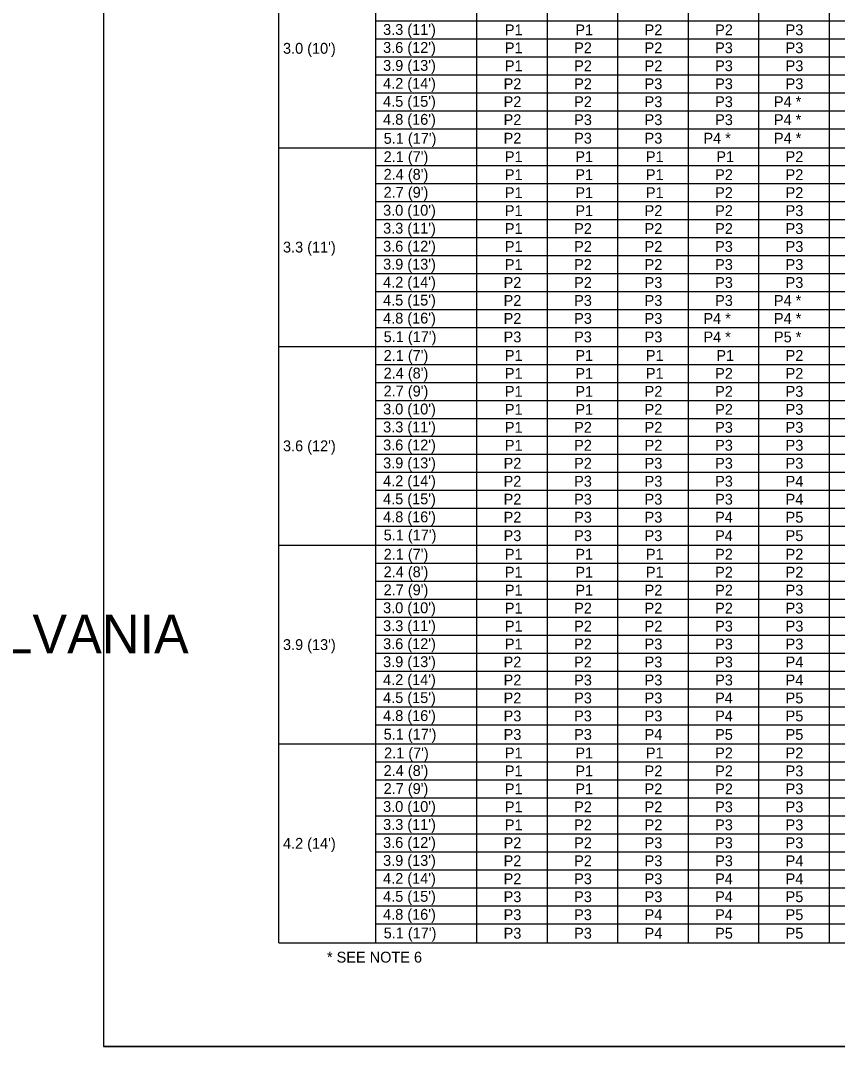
# Model space of a CAD drawing. Extents: x 637580 to 641008, y 294594 to 295782.
# Drawn here: x 638438.3 to 638664.4, y 295202.6 to 295486.5 of the extents above; entities that cross this region are included whole.
import ezdxf

# ---------------------------------------------------------------- set-up
doc = ezdxf.new("R2010")
doc.units = 0
doc.layers.add('1', color=7, linetype='Continuous')
doc.layers.add('2', color=7, linetype='Continuous')

msp = doc.modelspace()

# ---------------------------------------------------------------- linework, layer by layer
at = {"layer": '1'}
for p, q in [((638461.31, 295766.63), (638461.31, 295202.63)), ((638509.81, 295231.34), (638509.81, 295750.63)), ((638536.61, 295231.34), (638536.61, 295742.95)), ((638564.61, 295231.34), (638564.61, 295742.95)), ((638584.12, 295231.34), (638584.12, 295735.61)), ((638603.63, 295231.34), (638603.63, 295735.61)), ((638623.14, 295231.34), (638623.14, 295735.61)), ((638642.64, 295231.34), (638642.64, 295735.61)), ((638662.15, 295231.34), (638662.15, 295735.61)), ((638509.81, 295451.3), (638876.73, 295451.3)), ((638509.81, 295396.31), (638876.73, 295396.31)), ((638509.81, 295341.32), (638876.73, 295341.32)), ((638509.81, 295286.33), (638876.73, 295286.33)), ((638509.81, 295231.34), (638876.73, 295231.34)), ((639247.31, 295202.63), (638461.31, 295202.63)), ((638461.31, 295202.63), (639047.31, 295202.63))]:
    msp.add_line(p, q, dxfattribs=at)
at = {"layer": '2'}
for p, q in [((638536.61, 295486.4), (638876.73, 295486.4)), ((638536.61, 295481.43), (638876.73, 295481.43)), ((638536.61, 295476.45), (638876.73, 295476.45)), ((638536.61, 295471.48), (638876.73, 295471.48)), ((638536.61, 295466.51), (638876.73, 295466.51)), ((638536.61, 295461.54), (638876.73, 295461.54)), ((638536.61, 295456.56), (638876.73, 295456.56)), ((638536.61, 295446.33), (638876.73, 295446.33)), ((638536.61, 295441.35), (638876.73, 295441.35)), ((638536.61, 295436.38), (638876.73, 295436.38)), ((638536.61, 295431.41), (638876.73, 295431.41)), ((638536.61, 295426.44), (638876.73, 295426.44)), ((638536.61, 295421.46), (638876.73, 295421.46)), ((638536.61, 295416.49), (638876.73, 295416.49)), ((638536.61, 295411.52), (638876.73, 295411.52)), ((638536.61, 295406.55), (638876.73, 295406.55)), ((638536.61, 295401.57), (638876.73, 295401.57)), ((638536.61, 295391.34), (638876.73, 295391.34)), ((638536.61, 295386.36), (638876.73, 295386.36)), ((638536.61, 295381.39), (638876.73, 295381.39)), ((638536.61, 295376.42), (638876.73, 295376.42)), ((638536.61, 295371.45), (638876.73, 295371.45)), ((638536.61, 295366.47), (638876.73, 295366.47)), ((638536.61, 295361.5), (638876.73, 295361.5)), ((638536.61, 295356.53), (638876.73, 295356.53)), ((638536.61, 295351.56), (638876.73, 295351.56)), ((638536.61, 295346.58), (638876.73, 295346.58)), ((638536.61, 295336.35), (638876.73, 295336.35)), ((638536.61, 295331.37), (638876.73, 295331.37)), ((638536.61, 295326.4), (638876.73, 295326.4)), ((638536.61, 295321.43), (638876.73, 295321.43)), ((638536.61, 295316.46), (638876.73, 295316.46)), ((638536.61, 295311.48), (638876.73, 295311.48)), ((638536.61, 295306.51), (638876.73, 295306.51)), ((638536.61, 295301.54), (638876.73, 295301.54)), ((638536.61, 295296.57), (638876.73, 295296.57)), ((638536.61, 295291.59), (638876.73, 295291.59)), ((638536.61, 295281.36), (638876.73, 295281.36)), ((638536.61, 295276.38), (638876.73, 295276.38)), ((638536.61, 295271.41), (638876.73, 295271.41)), ((638536.61, 295266.44), (638876.73, 295266.44)), ((638536.61, 295261.47), (638876.73, 295261.47)), ((638536.61, 295256.49), (638876.73, 295256.49)), ((638536.61, 295251.52), (638876.73, 295251.52)), ((638536.61, 295246.55), (638876.73, 295246.55)), ((638536.61, 295241.58), (638876.73, 295241.58)), ((638536.61, 295236.6), (638876.73, 295236.6))]:
    msp.add_line(p, q, dxfattribs=at)

# ---------------------------------------------------------------- texts
at = {"layer": '1'}
for s, height, p in [("3.3 (11')", 3, (638538.67, 295482.51)), ('P1', 3, (638572.36, 295482.41)), ('P1', 3, (638591.87, 295482.41)), ('P2', 3, (638611.03, 295482.41)), ('P2', 3, (638630.54, 295482.41)), ('P3', 3, (638650.05, 295482.41)), ("3.0 (10')", 3, (638510.97, 295477.29)), ("3.6 (12')", 3, (638538.67, 295477.53)), ('P1', 3, (638572.36, 295477.44)), ('P2', 3, (638591.53, 295477.44)), ('P2', 3, (638611.03, 295477.44)), ('P3', 3, (638630.54, 295477.44)), ('P3', 3, (638650.05, 295477.44)), ("3.9 (13')", 3, (638538.67, 295472.56)), ('P1', 3, (638572.36, 295472.47)), ('P2', 3, (638591.53, 295472.47)), ('P2', 3, (638611.03, 295472.47)), ('P3', 3, (638630.54, 295472.47)), ('P3', 3, (638650.05, 295472.47)), ("4.2 (14')", 3, (638538.67, 295467.59)), ('P2', 3, (638572.02, 295467.49)), ('P2', 3, (638591.53, 295467.49)), ('P3', 3, (638611.03, 295467.49)), ('P3', 3, (638630.54, 295467.49)), ('P3', 3, (638650.05, 295467.49)), ("4.5 (15')", 3, (638538.67, 295462.62)), ('P2', 3, (638572.02, 295462.52)), ('P2', 3, (638591.53, 295462.52)), ('P3', 3, (638611.03, 295462.52)), ('P3', 3, (638630.54, 295462.52)), ('P4 *', 3, (638646.82, 295462.52)), ("4.8 (16')", 3, (638538.67, 295457.64)), ('P2', 3, (638572.02, 295457.55)), ('P3', 3, (638591.53, 295457.55)), ('P3', 3, (638611.03, 295457.55)), ('P3', 3, (638630.54, 295457.55)), ('P4 *', 3, (638646.82, 295457.55)), ("5.1 (17')", 3, (638538.83, 295452.37)), ('P2', 3, (638572.02, 295452.43)), ('P3', 3, (638591.53, 295452.43)), ('P3', 3, (638611.03, 295452.43)), ('P4 *', 3, (638627.31, 295452.43)), ('P4 *', 3, (638646.82, 295452.43)), ("2.1 (7')", 3, (638538.82, 295447.31)), ('P1', 3, (638572.36, 295447.31)), ('P1', 3, (638591.87, 295447.31)), ('P1', 3, (638611.38, 295447.31)), ('P1', 3, (638630.88, 295447.31)), ('P2', 3, (638650.05, 295447.31)), ("2.4 (8')", 3, (638538.82, 295442.43)), ('P1', 3, (638572.36, 295442.34)), ('P1', 3, (638591.87, 295442.34)), ('P1', 3, (638611.38, 295442.34)), ('P2', 3, (638630.54, 295442.34)), ('P2', 3, (638650.05, 295442.34)), ("2.7 (9')", 3, (638538.82, 295437.46)), ('P1', 3, (638572.36, 295437.37)), ('P1', 3, (638591.87, 295437.37)), ('P1', 3, (638611.38, 295437.37)), ('P2', 3, (638630.54, 295437.37)), ('P2', 3, (638650.05, 295437.37)), ("3.0 (10')", 3, (638538.67, 295432.49)), ('P1', 3, (638572.36, 295432.39)), ('P1', 3, (638591.87, 295432.39)), ('P2', 3, (638611.03, 295432.39)), ('P2', 3, (638630.54, 295432.39)), ('P3', 3, (638650.05, 295432.39)), ("3.3 (11')", 3, (638538.67, 295427.52)), ('P1', 3, (638572.36, 295427.42)), ('P2', 3, (638591.53, 295427.42)), ('P2', 3, (638611.03, 295427.42)), ('P2', 3, (638630.54, 295427.42)), ('P3', 3, (638650.05, 295427.42)), ("3.3 (11')", 3, (638510.97, 295422.3)), ("3.6 (12')", 3, (638538.67, 295422.54)), ('P1', 3, (638572.36, 295422.45)), ('P2', 3, (638591.53, 295422.45)), ('P2', 3, (638611.03, 295422.45)), ('P3', 3, (638630.54, 295422.45)), ('P3', 3, (638650.05, 295422.45)), ("3.9 (13')", 3, (638538.67, 295417.57)), ('P1', 3, (638572.36, 295417.48)), ('P2', 3, (638591.53, 295417.48)), ('P2', 3, (638611.03, 295417.48)), ('P3', 3, (638630.54, 295417.48)), ('P3', 3, (638650.05, 295417.48)), ("4.2 (14')", 3, (638538.67, 295412.6)), ('P2', 3, (638572.02, 295412.5)), ('P2', 3, (638591.53, 295412.5)), ('P3', 3, (638611.03, 295412.5)), ('P3', 3, (638630.54, 295412.5)), ('P3', 3, (638650.05, 295412.5)), ("4.5 (15')", 3, (638538.67, 295407.63)), ('P2', 3, (638572.02, 295407.53)), ('P3', 3, (638591.53, 295407.53)), ('P3', 3, (638611.03, 295407.53)), ('P3', 3, (638630.54, 295407.53)), ('P4 *', 3, (638646.82, 295407.53)), ("4.8 (16')", 3, (638538.67, 295402.65)), ('P2', 3, (638572.02, 295402.56)), ('P3', 3, (638591.53, 295402.56)), ('P3', 3, (638611.03, 295402.56)), ('P4 *', 3, (638627.31, 295402.56)), ('P4 *', 3, (638646.82, 295402.56)), ("5.1 (17')", 3, (638538.83, 295397.5)), ('P3', 3, (638572.02, 295397.44)), ('P3', 3, (638591.53, 295397.44)), ('P3', 3, (638611.03, 295397.44)), ('P4 *', 3, (638627.31, 295397.44)), ('P5 *', 3, (638646.82, 295397.44)), ("2.1 (7')", 3, (638538.82, 295392.32)), ('P1', 3, (638572.36, 295392.32)), ('P1', 3, (638591.87, 295392.32)), ('P1', 3, (638611.38, 295392.32)), ('P1', 3, (638630.88, 295392.32)), ('P2', 3, (638650.05, 295392.32)), ("2.4 (8')", 3, (638538.82, 295387.44)), ('P1', 3, (638572.36, 295387.35)), ('P1', 3, (638591.87, 295387.35)), ('P1', 3, (638611.38, 295387.35)), ('P2', 3, (638630.54, 295387.35)), ('P2', 3, (638650.05, 295387.35)), ("2.7 (9')", 3, (638538.82, 295382.47)), ('P1', 3, (638572.36, 295382.38)), ('P1', 3, (638591.87, 295382.38)), ('P2', 3, (638611.03, 295382.38)), ('P2', 3, (638630.54, 295382.38)), ('P3', 3, (638650.05, 295382.38)), ("3.0 (10')", 3, (638538.67, 295377.5)), ('P1', 3, (638572.36, 295377.4)), ('P1', 3, (638591.87, 295377.4)), ('P2', 3, (638611.03, 295377.4)), ('P2', 3, (638630.54, 295377.4)), ('P3', 3, (638650.05, 295377.4)), ("3.3 (11')", 3, (638538.67, 295372.53)), ('P1', 3, (638572.36, 295372.43)), ('P2', 3, (638591.53, 295372.43)), ('P2', 3, (638611.03, 295372.43)), ('P3', 3, (638630.54, 295372.43)), ('P3', 3, (638650.05, 295372.43)), ("3.6 (12')", 3, (638538.67, 295367.55)), ("3.6 (12')", 3, (638510.97, 295367.31)), ('P1', 3, (638572.36, 295367.46)), ('P2', 3, (638591.53, 295367.46)), ('P2', 3, (638611.03, 295367.46)), ('P3', 3, (638630.54, 295367.46)), ('P3', 3, (638650.05, 295367.46)), ("3.9 (13')", 3, (638538.67, 295362.58)), ('P2', 3, (638572.02, 295362.49)), ('P2', 3, (638591.53, 295362.49)), ('P3', 3, (638611.03, 295362.49)), ('P3', 3, (638630.54, 295362.49)), ('P3', 3, (638650.05, 295362.49)), ("4.2 (14')", 3, (638538.67, 295357.61)), ('P2', 3, (638572.02, 295357.51)), ('P3', 3, (638591.53, 295357.51)), ('P3', 3, (638611.03, 295357.51)), ('P3', 3, (638630.54, 295357.51)), ('P4', 3, (638650.05, 295357.51)), ("4.5 (15')", 3, (638538.67, 295352.64)), ('P2', 3, (638572.02, 295352.54)), ('P3', 3, (638591.53, 295352.54)), ('P3', 3, (638611.03, 295352.54)), ('P3', 3, (638630.54, 295352.54)), ('P4', 3, (638650.05, 295352.54)), ("4.8 (16')", 3, (638538.67, 295347.66)), ('P2', 3, (638572.02, 295347.57)), ('P3', 3, (638591.53, 295347.57)), ('P3', 3, (638611.03, 295347.57)), ('P4', 3, (638630.54, 295347.57)), ('P5', 3, (638650.05, 295347.57)), ("5.1 (17')", 3, (638538.83, 295342.64)), ('P3', 3, (638572.02, 295342.45)), ('P3', 3, (638591.53, 295342.45)), ('P3', 3, (638611.03, 295342.45)), ('P4', 3, (638630.54, 295342.45)), ('P5', 3, (638650.05, 295342.45)), ("2.1 (7')", 3, (638538.82, 295337.33)), ('P1', 3, (638572.36, 295337.33)), ('P1', 3, (638591.87, 295337.33)), ('P1', 3, (638611.38, 295337.33)), ('P2', 3, (638630.54, 295337.33)), ('P2', 3, (638650.05, 295337.33)), ("2.4 (8')", 3, (638538.82, 295332.45)), ('P1', 3, (638572.36, 295332.36)), ('P1', 3, (638591.87, 295332.36)), ('P1', 3, (638611.38, 295332.36)), ('P2', 3, (638630.54, 295332.36)), ('P2', 3, (638650.05, 295332.36)), ("2.7 (9')", 3, (638538.82, 295327.48)), ('P1', 3, (638572.36, 295327.39)), ('P1', 3, (638591.87, 295327.39)), ('P2', 3, (638611.03, 295327.39)), ('P2', 3, (638630.54, 295327.39)), ('P3', 3, (638650.05, 295327.39)), ("3.0 (10')", 3, (638538.67, 295322.51)), ('P1', 3, (638572.36, 295322.41)), ('P2', 3, (638591.53, 295322.41)), ('P2', 3, (638611.03, 295322.41)), ('P2', 3, (638630.54, 295322.41)), ('P3', 3, (638650.05, 295322.41)), ('COMMONWEALTH OF PENNSYLVANIA', 10.7828, (638218.9, 295311.36)), ("3.3 (11')", 3, (638538.67, 295317.54)), ('P1', 3, (638572.36, 295317.44)), ('P2', 3, (638591.53, 295317.44)), ('P2', 3, (638611.03, 295317.44)), ('P3', 3, (638630.54, 295317.44)), ('P3', 3, (638650.05, 295317.44)), ("3.9 (13')", 3, (638510.97, 295312.32)), ("3.6 (12')", 3, (638538.67, 295312.56)), ('P1', 3, (638572.36, 295312.47)), ('P2', 3, (638591.53, 295312.47)), ('P3', 3, (638611.03, 295312.47)), ('P3', 3, (638630.54, 295312.47)), ('P3', 3, (638650.05, 295312.47)), ("3.9 (13')", 3, (638538.67, 295307.59)), ('P2', 3, (638572.02, 295307.5)), ('P2', 3, (638591.53, 295307.5)), ('P3', 3, (638611.03, 295307.5)), ('P3', 3, (638630.54, 295307.5)), ('P4', 3, (638650.05, 295307.5)), ("4.2 (14')", 3, (638538.67, 295302.62)), ('P2', 3, (638572.02, 295302.52)), ('P3', 3, (638591.53, 295302.52)), ('P3', 3, (638611.03, 295302.52)), ('P3', 3, (638630.54, 295302.52)), ('P4', 3, (638650.05, 295302.52)), ("4.5 (15')", 3, (638538.67, 295297.65)), ('P2', 3, (638572.02, 295297.55)), ('P3', 3, (638591.53, 295297.55)), ('P3', 3, (638611.03, 295297.55)), ('P4', 3, (638630.54, 295297.55)), ('P5', 3, (638650.05, 295297.55)), ("4.8 (16')", 3, (638538.67, 295292.67)), ('P3', 3, (638572.02, 295292.58)), ('P3', 3, (638591.53, 295292.58)), ('P3', 3, (638611.03, 295292.58)), ('P4', 3, (638630.54, 295292.58)), ('P5', 3, (638650.05, 295292.58)), ("5.1 (17')", 3, (638538.83, 295287.52)), ('P3', 3, (638572.02, 295287.46)), ('P3', 3, (638591.53, 295287.46)), ('P4', 3, (638611.03, 295287.46)), ('P5', 3, (638630.54, 295287.46)), ('P5', 3, (638650.05, 295287.46)), ("2.1 (7')", 3, (638538.94, 295282.34)), ('P1', 3, (638572.36, 295282.34)), ('P1', 3, (638591.87, 295282.34)), ('P1', 3, (638611.38, 295282.34)), ('P2', 3, (638630.54, 295282.34)), ('P2', 3, (638650.05, 295282.34)), ("2.4 (8')", 3, (638538.82, 295277.46)), ('P1', 3, (638572.36, 295277.37)), ('P1', 3, (638591.87, 295277.37)), ('P2', 3, (638611.03, 295277.37)), ('P2', 3, (638630.54, 295277.37)), ('P3', 3, (638650.05, 295277.37)), ("2.7 (9')", 3, (638538.82, 295272.49)), ('P1', 3, (638572.36, 295272.4)), ('P1', 3, (638591.87, 295272.4)), ('P2', 3, (638611.03, 295272.4)), ('P2', 3, (638630.54, 295272.4)), ('P3', 3, (638650.05, 295272.4)), ("3.0 (10')", 3, (638538.67, 295267.52)), ('P1', 3, (638572.36, 295267.42)), ('P2', 3, (638591.53, 295267.42)), ('P2', 3, (638611.03, 295267.42)), ('P3', 3, (638630.54, 295267.42)), ('P3', 3, (638650.05, 295267.42)), ("3.3 (11')", 3, (638538.67, 295262.55)), ('P1', 3, (638572.36, 295262.45)), ('P2', 3, (638591.53, 295262.45)), ('P2', 3, (638611.03, 295262.45)), ('P3', 3, (638630.54, 295262.45)), ('P3', 3, (638650.05, 295262.45)), ("4.2 (14')", 3, (638510.97, 295257.33)), ("3.6 (12')", 3, (638538.67, 295257.57)), ('P2', 3, (638572.02, 295257.48)), ('P2', 3, (638591.53, 295257.48)), ('P3', 3, (638611.03, 295257.48)), ('P3', 3, (638630.54, 295257.48)), ('P3', 3, (638650.05, 295257.48)), ("3.9 (13')", 3, (638538.67, 295252.6)), ('P2', 3, (638572.02, 295252.51)), ('P2', 3, (638591.53, 295252.51)), ('P3', 3, (638611.03, 295252.51)), ('P3', 3, (638630.54, 295252.51)), ('P4', 3, (638650.05, 295252.51)), ("4.2 (14')", 3, (638538.67, 295247.63)), ('P2', 3, (638572.02, 295247.53)), ('P3', 3, (638591.53, 295247.53)), ('P3', 3, (638611.03, 295247.53)), ('P4', 3, (638630.54, 295247.53)), ('P4', 3, (638650.05, 295247.53)), ("4.5 (15')", 3, (638538.67, 295242.66)), ('P3', 3, (638572.02, 295242.56)), ('P3', 3, (638591.53, 295242.56)), ('P3', 3, (638611.03, 295242.56)), ('P4', 3, (638630.54, 295242.56)), ('P5', 3, (638650.05, 295242.56)), ("4.8 (16')", 3, (638538.67, 295237.68)), ('P3', 3, (638572.02, 295237.59)), ('P3', 3, (638591.53, 295237.59)), ('P4', 3, (638611.03, 295237.59)), ('P4', 3, (638630.54, 295237.59)), ('P5', 3, (638650.05, 295237.59)), ("5.1 (17')", 3, (638538.83, 295232.53)), ('P3', 3, (638572.02, 295232.47)), ('P3', 3, (638591.53, 295232.47)), ('P4', 3, (638611.03, 295232.47)), ('P5', 3, (638630.54, 295232.47)), ('P5', 3, (638650.05, 295232.47)), ('* SEE NOTE 6', 3, (638523.13, 295225.84))]:
    msp.add_text(s, height=height, dxfattribs=at).set_placement(p)

doc.saveas('drawing.dxf')
